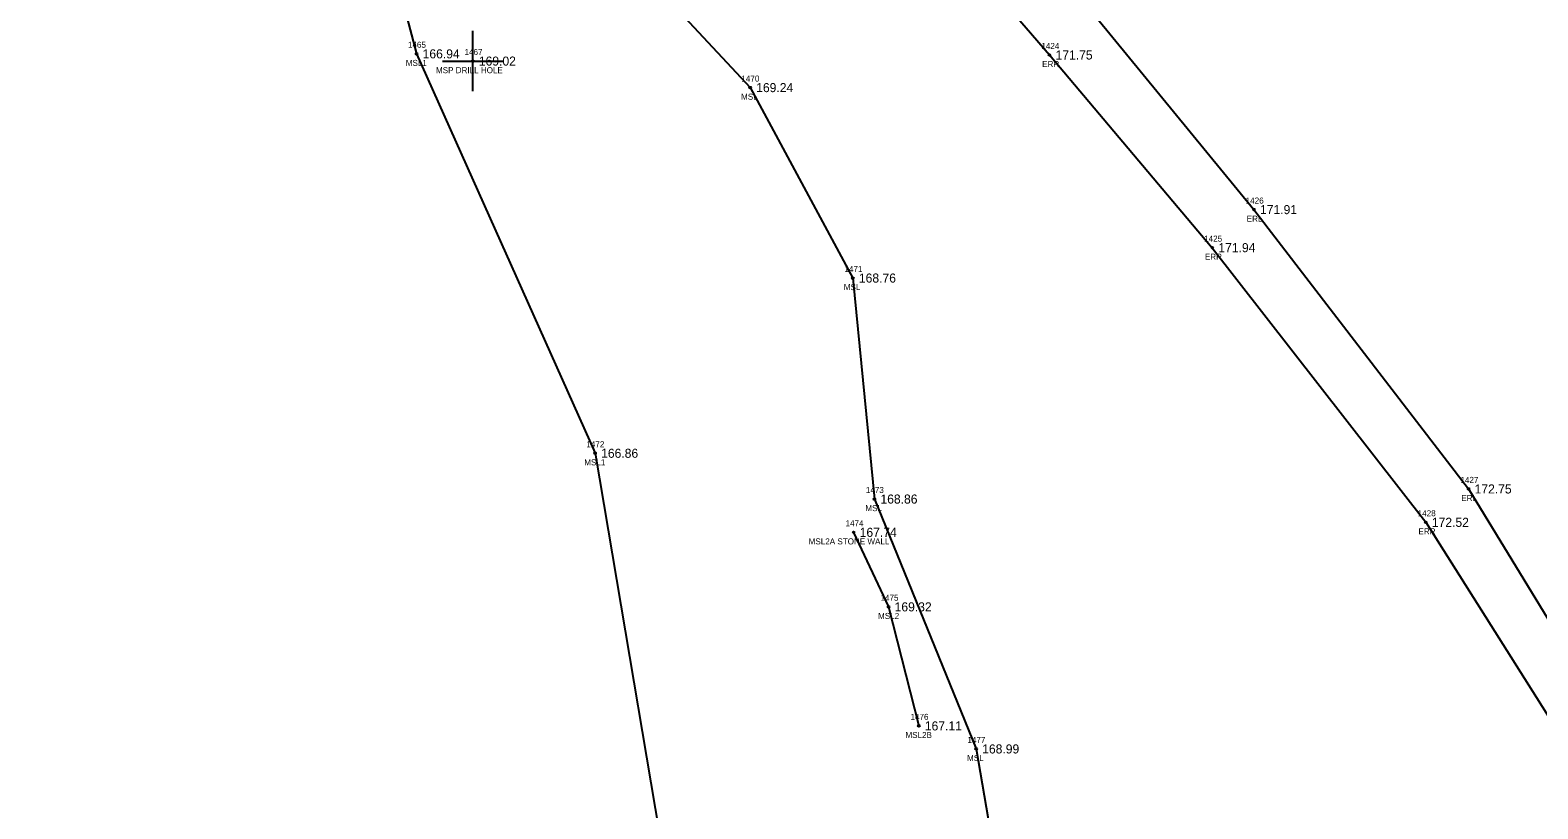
# Model space of a CAD drawing. Extents: x 1969685 to 1970577, y 796315 to 797503.
# Drawn here: x 1970128.7 to 1970378.4, y 796709.2 to 796838.1 of the extents above; entities that cross this region are included whole.
import ezdxf

# ---------------------------------------------------------------- set-up
doc = ezdxf.new("R2010")
doc.units = 0
for name, color, linetype in [('RD_EX_Misc', 7, 'Continuous'), ('RD_EX_Misc_txCode', 7, 'Continuous'), ('RD_EX_Road', 7, 'Continuous'), ('RD_EX_Road_txCode', 7, 'Continuous'), ('RD_EX_TX_Misc_ELEV', 7, 'Continuous'), ('RD_EX_TX_Road_ELEV', 7, 'Continuous'), ('RD_SMD_Locator', 7, 'Continuous')]:
    doc.layers.add(name, color=color, linetype=linetype)

msp = doc.modelspace()

# ---------------------------------------------------------------- linework, layer by layer
at = {"layer": 'RD_EX_Misc'}
for p, q in [((1970202.04, 796827.96), (1970202.04, 796837.96)), ((1970197.04, 796832.96), (1970207.04, 796832.96))]:
    msp.add_line(p, q, dxfattribs=at)
for points in [[(1970119.68, 797002.07), (1970134.67, 796985.14), (1970155.26, 796957.98), (1970184.14, 796927.08), (1970200, 796908.86), (1970214.83, 796881.9), (1970223.07, 796860.85), (1970237.12, 796840.22), (1970247.97, 796828.57), (1970264.98, 796797.04), (1970268.55, 796760.45), (1970285.4, 796719.08), (1970289.98, 796692.37), (1970293.21, 796649.04), (1970312.17, 796610.64), (1970319.99, 796568.49), (1970324.17, 796540.99), (1970330.09, 796500.77), (1970344.67, 796440.73), (1970352.86, 796398.26), (1970358.68, 796366.34), (1970371.75, 796316.87)], [(1970114.12, 796963.3), (1970132.42, 796938.45), (1970155.62, 796908.35), (1970168.41, 796889.26), (1970180.37, 796861.1), (1970188.98, 796848.46), (1970192.73, 796834.16), (1970222.29, 796768.03), (1970236.51, 796684.05), (1970250.88, 796649.74), (1970268.59, 796625.9), (1970285.6, 796558.95), (1970297.61, 796519.29), (1970305.78, 796473.65), (1970318, 796423.32), (1970326.24, 796374.48), (1970344.95, 796321.79)], [(1970265.11, 796754.94), (1970270.9, 796742.6), (1970275.9, 796722.89)]]:
    msp.add_lwpolyline(points, dxfattribs=at)
at = {"layer": 'RD_EX_Road'}
for points in [[(1969700.74, 797501.33), (1969779.98, 797423.39), (1969814.72, 797391.2), (1969880.84, 797321.11), (1969950.92, 797234.98), (1970023.24, 797160.71), (1970094.63, 797082.52), (1970155.94, 797004.5), (1970226.04, 796929.95), (1970305.25, 796840.26), (1970331.41, 796808.37), (1970366.95, 796762.12), (1970420.55, 796674.34), (1970475.41, 796571.94), (1970519.62, 796482.24), (1970570.43, 796387.6)], [(1969686.81, 797489.23), (1969769.62, 797412.05), (1969806.95, 797381.52), (1969873.82, 797315.12), (1969942.63, 797227.86), (1970016.3, 797154.94), (1970086.97, 797075.58), (1970150.3, 796998.65), (1970220.21, 796923.5), (1970297.55, 796833.97), (1970324.51, 796802.07), (1970359.87, 796756.6), (1970413.8, 796671.17), (1970467.81, 796568.38), (1970512.42, 796477.88), (1970563.2, 796383.6)]]:
    msp.add_lwpolyline(points, dxfattribs=at)
at = {"layer": 'RD_SMD_Locator'}
for centre in [(1970192.73, 796834.16), (1970202.04, 796832.96), (1970297.55, 796833.97), (1970247.97, 796828.57), (1970331.41, 796808.37), (1970324.51, 796802.07), (1970264.98, 796797.04), (1970222.29, 796768.03), (1970268.55, 796760.45), (1970366.95, 796762.12), (1970359.87, 796756.6), (1970265.11, 796754.94), (1970270.9, 796742.6), (1970275.9, 796722.89), (1970285.4, 796719.08)]:
    msp.add_circle(centre, 0.15, dxfattribs=at)

# ---------------------------------------------------------------- texts
at = {"layer": 'RD_EX_Misc_txCode'}
for s, p in [('1465', (1970191.3, 796835.16)), ('MSL1', (1970190.94, 796832.16)), ('1467', (1970200.67, 796833.96)), ('MSP DRILL HOLE', (1970195.94, 796830.96)), ('1470', (1970246.52, 796829.57)), ('MSL', (1970246.47, 796826.57)), ('1471', (1970263.59, 796798.04)), ('MSL', (1970263.48, 796795.04)), ('1472', (1970220.85, 796769.03)), ('MSL1', (1970220.5, 796766.03)), ('1473', (1970267.13, 796761.45)), ('MSL', (1970267.05, 796758.45)), ('1474', (1970263.77, 796755.94)), ('MSL2A STONE WALL', (1970257.66, 796752.94)), ('1475', (1970269.56, 796743.6)), ('MSL2', (1970269.16, 796740.6)), ('1476', (1970274.53, 796723.89)), ('MSL2B', (1970273.69, 796720.89)), ('1477', (1970283.96, 796720.08)), ('MSL', (1970283.9, 796717.08))]:
    msp.add_text(s, height=1, dxfattribs=at).set_placement(p)
at = {"layer": 'RD_EX_Road_txCode'}
for s, p in [('1424', (1970296.21, 796834.97)), ('ERR', (1970296.33, 796831.97)), ('1426', (1970330.04, 796809.37)), ('ERL', (1970330.21, 796806.37)), ('1425', (1970323.16, 796803.07)), ('ERR', (1970323.28, 796800.07)), ('1427', (1970365.61, 796763.12)), ('ERL', (1970365.75, 796760.12)), ('1428', (1970358.53, 796757.6)), ('ERR', (1970358.65, 796754.6))]:
    msp.add_text(s, height=1, dxfattribs=at).set_placement(p)
at = {"layer": 'RD_EX_TX_Misc_ELEV'}
for s, p in [('166.94', (1970193.73, 796833.41)), ('169.02', (1970203.04, 796832.21)), ('169.24', (1970248.97, 796827.82)), ('168.76', (1970265.98, 796796.29)), ('166.86', (1970223.29, 796767.28)), ('168.86', (1970269.55, 796759.7)), ('167.74', (1970266.11, 796754.19)), ('169.32', (1970271.9, 796741.85)), ('167.11', (1970276.9, 796722.14)), ('168.99', (1970286.4, 796718.33))]:
    msp.add_text(s, height=1.5, dxfattribs=at).set_placement(p)
at = {"layer": 'RD_EX_TX_Road_ELEV'}
for s, p in [('171.75', (1970298.55, 796833.22)), ('171.91', (1970332.41, 796807.62)), ('171.94', (1970325.51, 796801.32)), ('172.75', (1970367.95, 796761.37)), ('172.52', (1970360.87, 796755.85))]:
    msp.add_text(s, height=1.5, dxfattribs=at).set_placement(p)

doc.saveas('drawing.dxf')
